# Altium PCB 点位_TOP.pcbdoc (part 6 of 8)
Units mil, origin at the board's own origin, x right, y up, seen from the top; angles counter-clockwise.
Board outline 5129 x 4161 mil, 8 copper layers (Top Layer, GND1, 内层2, VCC, 内层4, Inner5, GND2, Bottom Layer); 288 components, 452 nets, 2040 pads, 1119 vias.
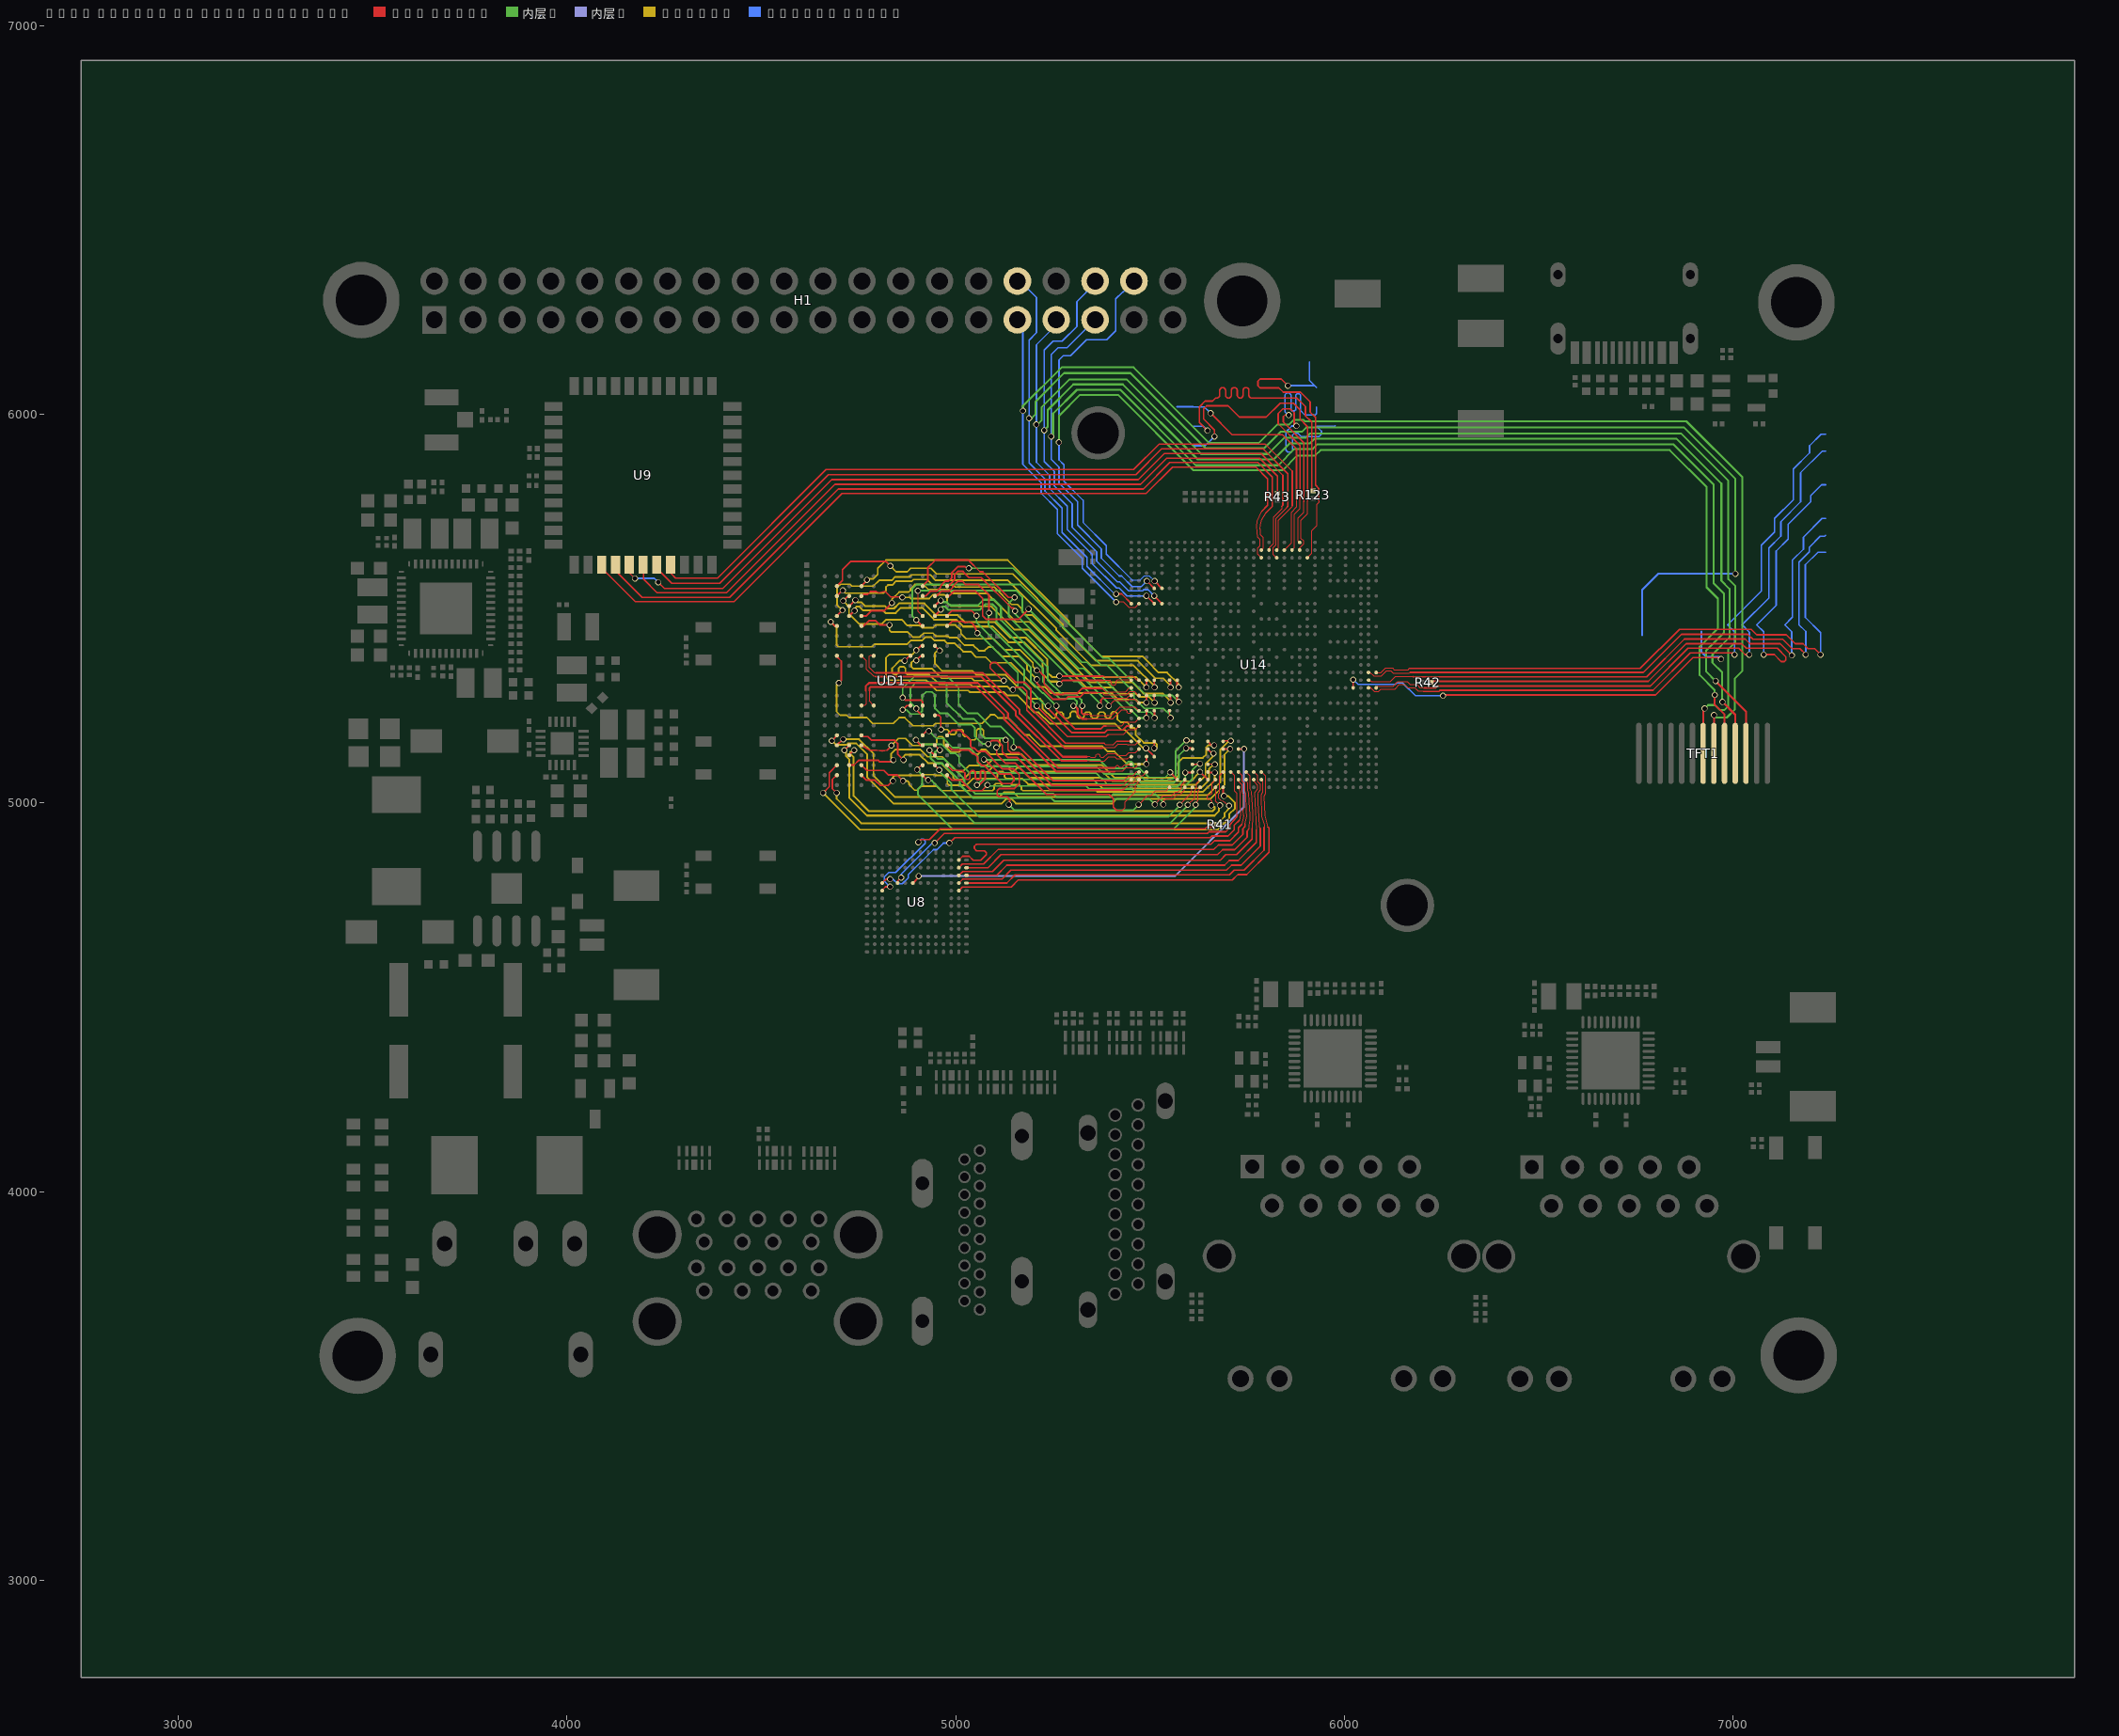
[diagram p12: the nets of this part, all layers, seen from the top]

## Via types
v1: diameter 15.75, hole 11.8, Top Layer to Bottom Layer, 496 vias
v2: diameter 15.7, hole 11.8, Top Layer to Bottom Layer, 335 vias
v3: diameter 15.75, hole 11.81, Top Layer to Bottom Layer, 279 vias
v4: diameter 24, hole 12, Top Layer to Bottom Layer, 9 vias

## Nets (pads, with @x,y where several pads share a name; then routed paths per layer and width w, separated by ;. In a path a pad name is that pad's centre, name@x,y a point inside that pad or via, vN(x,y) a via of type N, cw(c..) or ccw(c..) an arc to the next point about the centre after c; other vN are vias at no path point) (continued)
SAB5: U14.AL29 UD1.P11 | length 1061.5
  Top Layer w4: UD1.P11@4694.67,5379.22 4694.67,5376.22 4705.92,5364.97 4705.92,5314.97 v3(4699.92,5308.97)
  Top Layer w4.5: v3(5491.06,5100.23) U14.AL29@5491.06,5119.12
  Inner5 w4.5: v3(4699.92,5308.97) 4693.92,5302.97 4693.92,5234.97 4702.92,5225.97 4719.92,5225.97 4725.92,5219.97 4771.92,5219.97 4786.92,5204.97 4839.92,5204.97 4854.92,5219.97 4868.92,5219.97 4890.17,5198.72 4942.67,5198.72 4948.92,5204.97 5067.92,5204.97 5089.92,5226.97 5100.88,5226.97 5108.82,5219.03 5134.89,5218.96 5178.88,5174.97 5189.94,5174.97 5218.94,5145.97 5377.93,5145.97 5391.43,5132.47 5408.9,5132.47 5441.14,5100.23 v3(5491.06,5100.23)
SCKE0-A: U14.AM31 UD1.J4 | length 867.9
  Top Layer w3: 5432.47,5057.53 5444.82,5069.88 5455.73,5069.88 5465.6,5079.75 U14.AM31@5471.37,5079.75
  Top Layer w4.5: v3(4863.92,5270.97) 4869.92,5264.97 4910.63,5264.97 4915.14,5260.46 UD1.J4@4915.14,5251.26 ; v3(5149.31,5143.36) 5165.53,5143.36 5251.36,5057.53 5432.47,5057.53
  内层2 w4.5: v3(4863.92,5270.97) 4863.92,5295.97 4893.92,5325.97 4978.92,5325.97 5007.92,5296.97 5007.92,5252.97 5029.92,5230.97 5055.76,5230.97 5090.01,5196.72 5116.64,5196.72 5149.31,5164.05 v3(5149.31,5143.36)
SCKE0-B: U14.AN27 UD1.P4 | length 843.6
  Top Layer w3: 5382,5153.97 5387,5148.97 5404.93,5148.97 5414.45,5158.49
  Top Layer w3.8: 5414.45,5158.49 U14.AN27@5451.69,5158.49
  Top Layer w4.5: v3(4898.92,5366.97) 4911.17,5379.22 UD1.P4@4915.14,5379.22 ; v3(5123.91,5314.96) 5120.93,5314.96 5088.92,5346.97 5088.92,5355.47 5095.42,5361.97 5102.92,5361.97 5153.92,5310.97 5176.92,5310.97 5193.92,5293.97 5193.92,5242.97 5282.92,5153.97 5382,5153.97
  Inner5 w4.5: v3(4898.92,5366.97) 4892.42,5366.97 4885.92,5360.47 4885.92,5350.97 4890.92,5345.97 4938.92,5345.97 4963.92,5320.97 5041.9,5320.97 5047.91,5314.96 v3(5123.91,5314.96)
SCKE1-A: U14.AL31 UD1.J5 | length 883.1
  Top Layer w3: 5431.85,5034.48 5447.6,5050.24 5457.19,5050.24 5461.5,5054.55 5461.51,5064.09 5467.29,5069.88 5481.19,5069.88 U14.AL31@5491.06,5079.75
  Top Layer w4: v3(4863.92,5239.97) 4874.92,5250.97 4882.84,5250.97 4883.13,5251.26 UD1.J5@4883.64,5251.26
  Top Layer w4.5: v3(5083.92,5151.97) 5092.49,5160.54 5108.35,5160.54 5120.42,5148.47 5120.42,5130.96 5134.41,5116.97 5158.92,5116.97 5241.92,5033.97 5428.66,5033.97 5429.17,5034.48 5431.84,5034.48
  内层2 w4.5: v3(4863.92,5239.97) 4873.92,5239.97 4884.92,5228.97 4906.92,5228.97 4913.92,5235.97 4913.92,5275.97 4923.92,5285.97 4938.92,5285.97 4946.92,5277.97 4946.92,5242.97 4958.92,5230.97 4978.92,5230.97 5007.92,5201.97 5040.92,5201.97 5049.92,5192.97 5049.91,5170.98 5068.41,5152.47 5083.92,5152.47 v3(5083.92,5151.97)
SCKE1-B: U14.AM27 UD1.P5 | length 859.6
  Top Layer w3: 5377.52,5141.97 5407.92,5141.97 5417.54,5151.59 5440.3,5151.59 5443.27,5148.62 5461.5,5148.62 U14.AM27@5471.37,5158.49
  Top Layer w4.5: v3(4868.92,5365.97) 4882.17,5379.22 UD1.P5@4883.64,5379.22 ; v3(5147.41,5291.46) 5153.92,5297.97 5171.93,5297.97 5183.33,5286.57 5183.33,5238.57 5280.93,5140.97 5376.52,5140.97 5377.52,5141.97
  Inner5 w4.5: v3(4868.92,5365.97) 4855.92,5365.97 4836.92,5346.97 4836.92,5334.97 4840.92,5330.97 4848.74,5330.97 4853.24,5335.47 4853.24,5346.47 4857.74,5350.97 4866.74,5350.97 4871.24,5346.47 4871.24,5335.47 4875.74,5330.97 4931.92,5330.97 4956.92,5305.97 5036.39,5305.97 5042.39,5299.97 5132.92,5299.97 5141.43,5291.46 v3(5147.41,5291.46)
SCKN-A: U14.AN30 UD1.J9 | length 850.5
  Top Layer w3: UD1.J9@4757.66,5251.26 4766.13,5251.26 4769.41,5254.54 4769.41,5286.97 4768.41,5287.97 4768.41,5288.72 ; 5408.94,5090.97 5413.8,5095.83 5418.06,5095.83 5422.79,5091.1 5427.04,5091.1 5433.52,5097.58 5449.84,5097.58 U14.AN30@5451.69,5099.43
  Top Layer w5: 4768.41,5288.72 4768.41,5299.95 4777.26,5308.8 5057.09,5308.8 5134.92,5230.97 5134.92,5219.13 5263.08,5090.97 5408.94,5090.97
SCKN-B: U14.AN29 UD1.P9 | length 833.6
  Top Layer w3: UD1.P9@4757.66,5379.22 4770,5366.88 4770,5345.57 4788.36,5327.21 4791.05,5327.21 4792.05,5326.21 4794.4,5326.21 4795.4,5325.21 4795.78,5325.21 ; 5337.77,5108.97 5344.6,5108.97 5345.6,5107.97 5382.92,5107.97 5394.07,5119.12 5408.88,5119.12 5414,5114 5442.55,5113.99 5447.68,5119.12 U14.AN29@5451.69,5119.12
  Top Layer w5: 4795.78,5325.21 5065.53,5325.21 5154.92,5235.82 5154.92,5225.82 5271.77,5108.97 5337.77,5108.97
SCKP-A: U14.AM30 UD1.J8 | length 848.8
  Top Layer w3: 4778.41,5288.72 4778.41,5287.97 4777.41,5286.97 4777.41,5263.01 UD1.J8@4789.16,5251.26 ; 5408.94,5080.97 5428.91,5080.97 5437.52,5089.58 5461.51,5089.58 U14.AM30@5471.37,5099.43
  Top Layer w5: 4778.41,5288.72 4778.41,5295.8 4781.41,5298.8 5052.94,5298.8 5124.92,5226.82 5124.92,5214.98 5258.93,5080.97 5408.94,5080.97
SCKP-B: U14.AM28 UD1.P8 | length 861.4
  Top Layer w3: UD1.P8@4789.16,5379.22 4780,5379.22 4777,5376.22 4777,5349.89 4791.68,5335.21 4795.78,5335.21 ; 5337.77,5118.97 5345.92,5118.97 5348.92,5115.97 5357.36,5115.97 5360.36,5118.97 5360.36,5121.97 5363.36,5124.97 5369.36,5124.97 5372.36,5121.97 5372.36,5118.97 5375.36,5115.97 5379.6,5115.97 5390.21,5126.58 5410.63,5126.58 5410.74,5126.47 5411.42,5126.47 5416.29,5121.6 5437.54,5121.6 5444.7,5128.75 5461.32,5128.75 U14.AM28@5471.37,5138.8
  Top Layer w5: 4795.78,5335.21 5069.68,5335.21 5164.92,5239.97 5164.92,5229.97 5275.92,5118.97 5337.77,5118.97
SCS0-A: U14.AN32 UD1.H4 | length 826.4
  Top Layer w3: 5426.05,5045.97 5431.93,5045.97 5446.02,5060.06 U14.AN32@5451.69,5060.06
  Top Layer w4.5: v3(4898.92,5242.97) 4898.92,5239.97 4913.22,5225.67 UD1.H4@4915.14,5225.67 ; v3(5128.92,5161.97) 5134.92,5155.97 5134.92,5136.97 5142.92,5128.97 5163.92,5128.97 5246.92,5045.97 5426.05,5045.97
  内层2 w4.5: v3(4898.92,5242.97) 4883.92,5257.97 4883.92,5295.97 4898.92,5310.97 4972.42,5310.97 4976.92,5306.47 4976.92,5257.97 5018.42,5216.47 5046.93,5216.47 5064.42,5198.98 5064.42,5176.98 5074.43,5166.97 5123.92,5166.97 v3(5128.92,5161.97)
SCS0-B: U14.AK29 UD1.R4 | length 932.3
  Top Layer w4.5: v3(4898.92,5392.97) 4910.76,5404.81 UD1.R4@4915.14,5404.81 ; v3(5489.92,5140.97) 5510.74,5120.15 U14.AK29@5510.74,5119.12
  Inner5 w4.5: v3(4898.92,5392.97) 4887.92,5381.97 4828.92,5381.97 4820.92,5373.97 4820.92,5323.97 4828.92,5315.97 4923.92,5315.97 4950.53,5289.36 5032.49,5289.36 5036.38,5285.47 5124.42,5285.47 5132.92,5276.97 5158.92,5276.97 5202.92,5232.97 5213.99,5232.97 5242.49,5204.47 5409.42,5204.47 5425.92,5187.97 5435.92,5187.97 5482.92,5140.97 v3(5489.92,5140.97)
SCS1-A: U14.AM32 UD1.H3 | length 813.7
  Top Layer w3: 5428.92,4980.97 5434.61,4986.66 5434.61,5001.61 5461.54,5028.54 5461.54,5044.46 5471.36,5054.27 U14.AM32@5471.37,5060.06
  Top Layer w4.5: UD1.H3@4946.64,5225.67 4957.42,5225.67 4961.92,5221.17 4961.92,5189.97 v3(4962.92,5188.97) ; v3(5104.92,5142.97) 5105.92,5141.97 5105.92,5124.95 5127.9,5102.97 5152.92,5102.97 5233.92,5021.97 5394.92,5021.97 5405.92,5010.97 5405.92,4988.97 5413.92,4980.97 5428.92,4980.97
  Inner5 w4.5: v3(4962.92,5188.97) 4978.96,5188.97 4983.46,5184.47 4983.46,5180.47 4987.96,5175.97 4996.96,5175.97 5001.46,5180.47 5001.46,5184.47 5005.96,5188.97 5015.92,5188.97 5018.92,5185.97 5018.92,5175.47 5023.42,5170.97 5029.92,5170.97 5038.48,5162.41 5049.42,5162.41 5053.92,5166.91 5053.92,5186.47 5058.42,5190.97 5067.42,5190.97 5071.92,5186.47 5071.92,5171.47 5076.42,5166.97 5109.42,5166.97 5113.92,5162.47 5113.92,5147.47 5109.42,5142.97 v3(5104.92,5142.97)
SCS1-B: U14.AK27 UD1.R3 | length 886.5
  Top Layer w4: U14.AK27@5510.74,5158.49 5510.74,5141.15 v3(5510.92,5140.97)
  Top Layer w4.5: UD1.R3@4946.65,5404.81 4958.92,5392.54 v3(4958.92,5391.97)
  Inner5 w4.5: v3(4958.92,5391.97) 4952.92,5391.97 4946.92,5385.97 4946.92,5357.97 4964.92,5339.97 5043.41,5339.97 5053.41,5329.97 5129.07,5329.97 5191.06,5267.98 5217.47,5267.98 5223.67,5261.78 5223.67,5244.06 5249.76,5217.97 5254.26,5217.97 5258.76,5222.47 5258.76,5229.47 5263.26,5233.97 5272.26,5233.97 5276.76,5229.47 5276.76,5222.47 5281.26,5217.97 5290.26,5217.97 5294.76,5222.47 5294.76,5230.77 5299.27,5235.28 5308.25,5235.28 5312.76,5230.77 5312.76,5222.47 5317.26,5217.97 5326.26,5217.97 5330.76,5222.47 5330.76,5229.47 5335.26,5233.97 5344.26,5233.97 5348.76,5229.47 5348.76,5222.47 5353.26,5217.97 5362.26,5217.97 5366.76,5222.47 5366.76,5229.47 5371.26,5233.97 5380.26,5233.97 5384.76,5229.47 5384.76,5222.47 5389.26,5217.97 5395.42,5217.97 5399.92,5222.47 5399.92,5230.27 5404.74,5235.09 5411.11,5235.09 5415.92,5230.28 5415.92,5215.97 5423.92,5207.97 5440.92,5207.97 5445.92,5202.97 5445.92,5197.97 5450.17,5193.72 5458.67,5193.72 5462.92,5189.47 5462.92,5175.97 5483.92,5154.97 5513.92,5154.97 5518,5150.89 5518,5144.68 5514.3,5140.97 v3(5510.92,5140.97)
SDC0-CLK: R42.2 | length 1564.7
  Top Layer w4: R42.2@6224.51,5310 6227.51,5313 6782,5313 6879,5410 7022,5410 7034,5398 7114,5398 7136,5376 7136,5368 7132,5364 7124,5364 7106,5382 v1(7079,5382)
  Bottom Layer w4: v1(7079,5382) 7079,5440.4 7061,5458.4 7111,5508.4 7111,5648 7142,5679 7142,5717 7200,5775 7200,5791 7227.7,5818.7 7238.14,5818.7
SDC0-CMD: U14.B19 | length 1561
  Top Layer w3: U14.B19@6062.45,5315.17 6068.01,5315.17 6070.33,5312.84 6118.64,5312.84 6131.21,5325.4 6177.65,5325.4
  Top Layer w4: 6177.56,5325.26 6177.92,5324.9 6777.9,5324.9 6875,5422 7031,5422 7043,5410 7121,5410 v1(7151,5380)
  Bottom Layer w4: v1(7151,5380) 7151,5440.4 7133,5458.4 7153,5478.4 7153,5625 7181,5653 7181,5684 7229.09,5732.09 7238.14,5732.09
SDC0-D0: U14.A20 | length 1646.7
  Top Layer w3: U14.A20@6081.89,5296.31 6084.55,5298.97 6124.59,5298.97 6136.78,5311.15 6163.54,5311.15 6170.69,5304 6188,5304 6196,5296 6204,5296
  Top Layer w4: 6204,5296 6235,5296 6240,5301 6787,5301 6884,5398 7015,5398 7031,5382 v1(7042,5382)
  Bottom Layer w4: v1(7042,5382) 7042,5439.8 7023.24,5458.56 7092,5527.32 7092,5656 7123,5687 7123,5724 7174,5775 7174,5850 7229.31,5905.31 7238.14,5905.31
SDC0-D1: U14.B20 | length 1688.5
  Top Layer w3: U14.B20@6062.19,5296.31 6068.2,5296.31 6068.2,5296.1 6078.28,5286.02 6087.2,5286.02 6093.37,5292.19 6128.89,5292.19 6140.57,5303.87 6156.35,5303.87 6164.23,5296 6182,5296 6191,5287 6203,5287
  Top Layer w4: 6203,5287 6243,5287 6246,5290 6794,5290 6890,5386 7000,5386 v1(7004,5382)
  Bottom Layer w4: v1(7004,5382) 7004,5440.4 6986,5458.4 7073,5545.4 7073,5663 7107,5697 7107,5732 7155,5780 7155,5859 7197,5901 7197,5919 7226.62,5948.62 7238.14,5948.62
SDC0-D2: U14.A18 | length 1532.2
  Top Layer w3: U14.A18@6081.89,5335.71 6094.55,5335.71 6105.84,5347 6124,5347 6128,5343 6164,5343 6167,5346
  Top Layer w4: 6167,5346 6761,5346 6862,5447 7047,5447 7061,5433 7137,5433 7160,5410 7180,5410 7193,5397 7210,5397 v1(7225,5382)
  Bottom Layer w4: v1(7225,5382) 7225,5438.4 7186,5477.4 7186,5613 7218.48,5645.48 7238.14,5645.48
SDC0-D3: U14.B18 | length 1549.4
  Top Layer w3: U14.B18@6062.19,5335.71 6066.8,5335.71 6076.64,5325.84 6094.01,5325.84 6107.78,5339.61 6120.39,5339.61 6127,5333 6166,5333 6169,5336
  Top Layer w4: 6169,5336 6769,5336 6867,5434 7038,5434 7051,5421 7128,5421 7152,5397 7172,5397 v1(7187,5382)
  Bottom Layer w4: v1(7187,5382) 7187,5441.4 7170,5458.4 7170,5620 7196,5646 7196,5658 7224,5686 7235.35,5686 7238.14,5688.78
SDC0-DET: U14.D20 | length 1140.8
  Top Layer w4: U14.D20@6022.89,5296.4 v1(6022.89,5317.4) ; v1(6254,5276) 6256,5278 6801,5278 6897,5374 6965,5374 v2(6969,5370)
  Bottom Layer w4: v1(6022.89,5317.4) 6035.29,5305 6131,5305 6135,5309 6150,5309 6183,5276 v1(6254,5276)
  Bottom Layer w5: 6919,5441.49 6919,5388 6931,5376 6963,5376 v2(6969,5370)
SDC1-CLK: R43.2 U9.17 | length 1891.3
  Top Layer w4: U9.17@4197,5615.94 4197,5576 4232,5541 4411,5541 4690,5820 5476,5820 5543,5887 5782,5887 5828,5841 R43.2@5828,5797.51
SDC1-CMD: U9.16 U14.R2 | length 2095.3
  Top Layer w3: U14.R2@5806.29,5650.71 5806.29,5656.59 5816.72,5666.97 5816.72,5734.72 5839,5757 5839,5763
  Top Layer w4: U9.16@4161.57,5615.94 4161.57,5591.43 v1(4175,5578) ; v1(4235,5568) 4251,5552 4401,5552 4681,5832 5470,5832 5537,5899 5786,5899 5842,5843 5842,5766 5839,5763
  Bottom Layer w4: v1(4175,5578) 4225,5578 v1(4235,5568)
SDC1-D0: U9.18 U14.P3 | length 2057.5
  Top Layer w3: U14.P3@5825.99,5631.01 5816.12,5640.88 5816.12,5655.95 5823.22,5663.05 5823.22,5731.22 5852,5760 5852,5760.75
  Top Layer w4: U9.18@4232.43,5615.94 4232.43,5602.57 4270,5565 4393,5565 4673,5845 5464,5845 5530,5911 5791,5911 5855,5847 5855,5763.75 5852,5760.75
SDC1-D1: U9.19 U14.P2 | length 2019.1
  Top Layer w3: U14.P2@5825.99,5650.71 5829.72,5654.44 5829.72,5726.72 5866,5763 5866,5765
  Top Layer w4: U9.19@4267.87,5615.94 4267.87,5590.77 4279.64,5579 4388,5579 4667,5858 5458,5858 5523,5923 5797,5923 5866,5854 5866,5765
SDC1-D2: U9.14 U14.T3 | length 2137.9
  Top Layer w3: U14.T3@5786.59,5631.01 5776.74,5640.86 5776.74,5655.56 5783.04,5661.86 5783.04,5678.4 5777,5684.44 5776.36,5696.93 5774.27,5711.76 5775.66,5725.32 5782.5,5737.95 5788.52,5751.27
  Top Layer w4: U9.14@4090.7,5615.94 4090.7,5603.3 4176,5518 4430,5518 4708,5796 5490,5796 5558,5864 5773,5864 5803,5834 5803,5766 5788,5751
SDC1-D3: U9.15 U14.T2 | length 2097.3
  Top Layer w3: U14.T2@5786.59,5650.71 5790.2,5654.32 5790.2,5684.29 5783.77,5690.71 5783.77,5704.77 5784,5716.28 5788.64,5729.6 5797.79,5745.48
  Top Layer w4: U9.15@4126.13,5615.94 4126.13,5596.87 4194,5529 4419,5529 4698,5808 5483,5808 5551,5876 5778,5876 5815,5839 5815,5763 5798,5746
SDC2-CLK: R41.1 U8.M6 | length 1011.5
  Top Layer w4: U8.M6@4811.41,4774.52 4811.41,4776.41 4819.53,4784.53 v1(4831.42,4784.53) ; v1(4904,4899) 4911,4906 4933,4906 4961,4934 5642,4934 5646,4938 5663.8,4938 R41.1@5670.64,4944.85
  Bottom Layer w4: v1(4831.42,4784.53) 4817,4798.94 4817,4810 4828,4821 4846,4821 4921.67,4896.67 4921.67,4902.33 4917,4907 4912,4907 v1(4904,4899)
SDC2-CMD: U8.M5 U14.W33 | length 1093.4
  Top Layer w3: U14.W33@5726.25,5040.04 5728.34,5035.4 5731.12,5028.45 5731.43,5016.17 5731.43,5000.26 5732.66,4968.44 5729.65,4955.77
  Top Layer w4: U8.M5@4811.41,4794.22 4811.41,4794.41 4821.21,4804.21 v1(4831.42,4804.21) ; v1(4984,4897) 4998,4911 5655,4911 5659,4915 5701,4915 5717,4931 5717,4943 5729.75,4955.75
  Bottom Layer w4: v1(4831.42,4804.21) 4838.79,4804.21 4851,4792 4862.91,4792 4878,4807.09 4878,4815 4943,4880 4952,4880 4967.91,4895.91 4967.91,4897 v1(4984,4897)
SDC2-D0: U8.A3 U14.V32 | length 903.9
  Top Layer w3: U14.V32@5747.11,5058.35 5749.18,5053.6 5750.54,5052.31 5750.54,5033.24 5753.3,5025.74 5753.91,5004.13 5756.46,4969.3 5756.61,4957.09 5754.11,4942.85 5754.05,4933.47
  Top Layer w4: U8.A3@5027.95,4833.59 5083.59,4833.59 5117,4867 5674,4867 5687,4880 5718,4880 5750,4912 5750,4928.05 5754.29,4933.11
SDC2-D1: U8.A4 U14.U32 | length 948.8
  Top Layer w3: U14.U32@5766.98,5060.2 5766.98,5056.02 5776.61,5046.39 5776.36,5035.09 5769.09,5026.14 5769.44,5001.92 5773.38,4931.94
  Top Layer w4: U8.A4@5027.95,4813.9 5105.9,4813.9 5132,4840 5692,4840 5704,4852 5727,4852 5773.61,4898.61 5773.61,4931.76
SDC2-D2: U8.A5 U14.T32 | length 986.2
  Top Layer w3: U14.T32@5786.75,5060.37 5789.86,5057.26 5789.86,5051.25 5789.87,5050.77 5789.65,5027.27 5785.71,5020.67 5786.91,4965.86 5794,4943.09 5794,4938
  Top Layer w4: U8.A5@5027.95,4794.22 5028.17,4794 5132,4794 5153,4815 5705,4815 5717,4827 5742,4827 5793.57,4878.57 5793.57,4937.57 5794,4938
SDC2-D3: U8.B2 U14.W32 | length 968.8
  Top Layer w3: U14.W32@5727.65,5060.37 5727.65,5056.31 5737.54,5046.42 5737.54,5029.42 ; 5736.44,4945.01 5740.88,4968.17 5739.96,4981.96 5739.15,5021.81 5737.55,5029.33
  Top Layer w4: U8.B2@5008.27,4853.27 5018,4863 5035,4863 5045,4853 5065,4853 5079,4867 5079,4872 5074,4877 5054,4877 5048.33,4882.67 5048.33,4888.33 5054,4894 5656.85,4894 5665.85,4903 5706,4903 5728,4925 5728,4936.6 5736.4,4945
SDC2-D4: U8.B3 U14.W31 | length 937.5
  Top Layer w3: U14.W31@5727.65,5080.07 5737.5,5070.22 5737.5,5056.17 5744.04,5049.62 5744.04,5032.08 5746.83,5024.5 5748.05,4978.74 5749.21,4965.64 5744.93,4947.11
  Top Layer w4: U8.B3@5008.27,4833.59 5017.68,4843 5072,4843 5110,4881 5665,4881 5676,4892 5712,4892 5739,4919 5739,4933.77 5744.93,4939.7 5744.93,4947.11
SDC2-D5: U8.B4 U14.V31 | length 971.3
  Top Layer w3: U14.V31@5747.35,5080.07 5757.21,5070.21 5757.21,5036.45 5759.72,5029.45 5759.72,5029.32 5763.69,4975.14 5763.81,4965.32 5762.96,4934.72
  Top Layer w4: U8.B4@5008.27,4813.9 5018.37,4824 5095,4824 5124,4853 5681,4853 5695,4867 5723,4867 5763,4907 5763,4935
SDC2-D6: U8.B5 U14.U31 | length 1015.5
  Top Layer w3: U14.U31@5767.05,5080.07 5776.95,5070.17 5776.94,5055.25 5783.17,5049.02 5782.81,5032.72 5778.6,5027.54 5776.7,5024.33 5776.83,5002.14 5779.14,4963.67 5781.38,4938.57 5783.93,4935.4
  Top Layer w4: U8.B5@5008.27,4794.22 5018.05,4804 5119,4804 5142,4827 5697,4827 5710,4840 5735,4840 5784.03,4889.03 5784.03,4935.03
SDC2-D7: U8.B6 U14.T31 | length 1052.8
  Top Layer w3: U14.T31@5786.75,5080.07 5796.37,5070.45 5796.62,5023.49 5793.49,5017.59 5794.79,4968.06 5802.77,4938.87
  Top Layer w4: U8.B6@5008.27,4774.52 5017.74,4784 5143,4784 5161,4802 5712,4802 5726,4816 5749,4816 5806,4873 5806,4936 5803,4939
SDC2-DS: U8.H5 U14.W28 | length 1098
  Top Layer w5: U8.H5@4890.15,4794.22 4905,4809.06 v1(4905,4812) ; U14.W28@5727.61,5138.93 v1(5742,5138.93)
  内层4 w5: v1(4905,4812) 5564,4812 5742,4990 v1(5742,5138.93)
SDC2-RST: U8.K5 U14.Y31 | length 1079.3
  Top Layer w3: U14.Y31@5707.95,5080.07 5717.77,5070.25 5717.77,5030.88 5724.55,5024.1 5724.55,4968.45
  Top Layer w4: U8.K5@4850.78,4794.22 4850.78,4798.78 v1(4860,4808) ; v1(4946,4897) 4971,4922 5648,4922 5652,4926 5695,4926 5706,4937 5706,4945 5723.09,4963.56 5724.47,4968.59
  Bottom Layer w4: v1(4860,4808) 4860,4817 4940,4897 v1(4946,4897)
SDQ0: U14.AE28 UD1.E4 | length 860.7
  Top Layer w4.5: v3(4897.92,5161.97) 4897.92,5160.97 4909.99,5148.9 UD1.E4@4915.14,5148.9 ; v3(5592.97,5141.23) 5606.74,5141.23 U14.AE28@5609.17,5138.8
  内层2 w4.5: v3(4897.92,5161.97) 4899.92,5161.97 4910.92,5150.97 4963.92,5150.97 4986.89,5128 4999.89,5128 5008.92,5118.97 5008.92,5103.97 5035.42,5077.47 5360.76,5077.47 5376.76,5061.47 5467.42,5061.47 5477.36,5051.53 5560.48,5051.53 5574.92,5065.97 5574.92,5123.18 v3(5592.97,5141.23)
SDQ1: U14.AE27 UD1.F4 | length 841.5
  Top Layer w3: v3(5593.96,5161.23) 5596.71,5158.49 U14.AE27@5609.17,5158.49
  Top Layer w4.5: UD1.F4@4915.14,5174.49 4924.62,5183.97 4929.92,5183.97 4930.87,5184.92 v3(4931.4,5184.92)
  内层2 w3: 5483.92,5061.97 5486.92,5058.97 5544.92,5058.97 5547.92,5061.97
  内层2 w4.5: v3(4931.4,5184.92) 4950.35,5165.97 4968.92,5165.97 4992.42,5142.47 5008.76,5142.47 5010.78,5140.45 5036.55,5140.45 5057.17,5119.83 5057.17,5102.72 5065.92,5093.97 5362.92,5093.97 5382.42,5074.47 5471.42,5074.47 5483.92,5061.97 ; 5547.92,5061.97 5557.92,5061.97 5565.92,5069.97 5565.92,5133.97 5593.18,5161.23 v3(5593.96,5161.23)
SDQ2: U14.AG32 UD1.E2 | length 880.5
  Top Layer w4.5: UD1.E2@4978.13,5148.9 4990.47,5136.56 5033.33,5136.56 5042.89,5127 5048,5127 5056.92,5118.08 5056.92,5106.97 5066.92,5096.97 5072.92,5096.97 5119.92,5049.97 5142.92,5049.97 5149.92,5056.97 5149.92,5065.97 5140.92,5074.97 5112.92,5074.97 5075.92,5111.97 v3(5072.92,5111.97) ; v3(5552,5079) 5569.8,5061.17 U14.AG32@5569.8,5060.06
  内层2 w3: 5494.92,5067.97 5496.92,5065.97 5538.97,5065.97 v3(5552,5079)
  内层2 w4.5: v3(5072.92,5111.97) 5073.92,5110.97 5370.92,5110.97 5392.92,5088.97 5434.72,5088.97 5439.22,5093.47 5439.22,5101.47 5443.72,5105.97 5452.72,5105.97 5457.22,5101.47 5457.22,5093.47 5461.72,5088.97 5473.92,5088.97 5494.92,5067.97
SDQ3: U14.AH33 UD1.F2 | length 840.6
  Top Layer w3: v3(5470.92,4995.97) 5492.94,5018 5501,5018 5514.01,5031.01 5540.73,5031.01 U14.AH33@5550.11,5040.38
  Top Layer w4.5: UD1.F2@4978.13,5174.49 4990.63,5187 5012.89,5187 5038.92,5160.97 5038.92,5145.97 5043.42,5141.47 5047.92,5141.47 5056.42,5132.97 5075.26,5132.97 5120.26,5087.97 5148.92,5087.97 5163.92,5072.97 5163.92,5049.97 5150.92,5036.97 5111.92,5036.97 5106.92,5031.97 5106.92,5020.97 5111.92,5015.97 5132.92,5015.97 5138.92,5009.97 5138.92,4997.97 v3(5136.92,4995.97)
  内层2 w4.5: v3(5136.92,4995.97) 5151.67,4981.22 5456.17,4981.22 v3(5470.92,4995.97)
SDQ4: U14.AE30 UD1.B2 | length 740.8
  Top Layer w4.5: UD1.B2@4978.13,5072.13 4991.29,5058.97 5013.92,5058.97 5040.92,5031.97 5067.67,5031.97 v3(5081.92,5046.22) ; U14.AE30@5609.17,5099.43 5627.38,5099.43 v3(5628.92,5100.97)
  内层2 w4.5: v3(5081.92,5046.22) 5084.17,5043.97 5335.92,5043.97 5343.92,5035.97 5453.92,5035.97 5456.92,5032.97 5579.92,5032.97 5608.92,5061.97 5608.92,5084.97 5624.92,5100.97 v3(5628.92,5100.97)
SDQ5: U14.AD32 UD1.B4 | length 831.9
  Top Layer w3: v3(5597.44,4995.51) 5613.77,5011.84 5613.77,5031.09 5618.99,5036.31 5618.99,5050.2 U14.AD32@5628.85,5060.06
  Top Layer w4.5: UD1.B4@4915.14,5072.13 4927.3,5059.97 4928.92,5059.97 v3@4929.54,5059.35
  内层2 w4.5: v3(4929.63,5059.35) 4931.31,5057.67 4939.22,5057.67 5048.67,4948.22 5552.15,4948.22 5597.44,4993.51 v3(5597.44,4995.51)
SDQ6: U14.AE31 UD1.C2 | length 817.4
  Top Layer w4.5: UD1.C2@4978.13,5097.72 4991.88,5083.97 5017.17,5083.97 5023.92,5077.22 5023.92,5064.97 5027.92,5060.97 5033.92,5060.97 5036.92,5063.97 5036.92,5079.47 5041.42,5083.97 5046.42,5083.97 5050.92,5079.47 5050.92,5063.97 5054.27,5060.62 5060.92,5060.62 5063.92,5063.62 5063.92,5080.97 5066.92,5083.97 5071.92,5083.97 5075.92,5079.97 5075.92,5060.97 5061.17,5046.22 v3(5054.92,5046.22) ; v3(5590.85,5078.25) 5607.68,5078.25 U14.AE31@5609.17,5079.75
  内层2 w4.5: v3(5054.92,5046.22) 5069.67,5060.97 5353.92,5060.97 5366.92,5047.97 5464.92,5047.97 5470.92,5041.97 5568.92,5041.97 5590.85,5063.9 v3(5590.85,5078.25)
SDQ7: U14.AD33 UD1.C4 | length 924.5
  Top Layer w3: v3(5617.54,4995.41) 5617.54,5000.4 5621.99,5004.85 5621.99,5029.2 5625.85,5033.06 5625.85,5037.38 U14.AD33@5628.85,5040.38
  Top Layer w4.5: v3(4900.92,5085.97) 4912.67,5097.72 UD1.C4@4915.14,5097.72
  内层2 w4.5: v3(4900.92,5085.97) 4913.92,5072.97 4913.92,5045.97 4902.92,5034.97 4902.92,5021.97 4993.17,4931.72 5559.67,4931.72 5617.54,4989.59 v3(5617.54,4995.41)
SDQ8: U14.AC27 UD1.E9 | length 1106.2
  Top Layer w4.5: UD1.E9@4757.8,5148.53 4779,5136 4797,5136 4811,5134 4824,5136 v3(4834.92,5147.97) ; U14.AC27@5648.54,5158.49 5658.8,5148.23 v3(5664.97,5148.23)
  Inner5 w4.5: v3(4834.92,5147.97) 4852.92,5165.97 4870.92,5165.97 4888.92,5147.97 4913.92,5147.97 4916.92,5150.97 4947.42,5150.97 4951.92,5155.47 4951.92,5166.47 4956.42,5170.97 4965.42,5170.97 4969.92,5166.47 4969.92,5149.97 4988.92,5130.97 5008.92,5130.97 5015.92,5137.97 5040.15,5137.97 5044.65,5133.47 5044.65,5130.47 5049.15,5125.97 5058.15,5125.97 5062.65,5130.47 5062.65,5133.47 5067.15,5137.97 5076.92,5137.97 5088.92,5125.97 5169.02,5125.97 5197.02,5097.97 5375.93,5097.97 5409.18,5064.72 5567.67,5064.72 5572.92,5069.97 5572.92,5103.97 5584.92,5115.97 5635.92,5115.97 5644.92,5124.97 5644.92,5143.72 5649.43,5148.23 v3(5664.97,5148.23)
SDQ9: U14.AC28 UD1.F9 | length 1107.7
  Top Layer w4.5: UD1.F9@4757.66,5174.49 4761.18,5170.97 4774.3,5170.97 4783.3,5161.97 4841.92,5161.97 4850.92,5152.97 4850.92,5125.97 v3(4865.92,5110.97) ; U14.AC28@5648.54,5138.8 5659.73,5127.61 v3(5663.64,5127.61)
  Inner5 w4.5: v3(4865.92,5110.97) 4865.92,5119.47 4870.42,5123.97 4907.92,5123.97 4928.92,5102.97 4961.92,5102.97 4993.92,5070.97 4993.92,5065.47 4998.42,5060.97 5020.08,5060.97 5039,5079.89 5082.84,5079.89 5098.92,5095.97 5134.42,5095.97 5138.92,5091.47 5138.92,5085.97 5143.92,5080.97 5148.92,5080.97 5158.23,5090.28 5164.61,5090.28 5189.92,5064.97 5373.92,5064.97 5391.92,5046.97 5618.92,5046.97 5642.92,5070.97 5642.92,5100.97 5663.64,5121.69 v3(5663.64,5127.61)
SDQ10: U14.AC30 UD1.B9 | length 1059.2
  Top Layer w3: U14.AC30@5648.54,5099.43 5648.72,5099.25 v3(5666.84,5099.25)
  Top Layer w4.5: UD1.B9@4757.66,5072.13 4770.82,5058.97 4792.92,5058.97 4806.92,5044.97 4826.92,5044.97 v3(4838.92,5056.97)
  Inner5 w4.5: v3(4838.92,5056.97) 4838.92,5066.47 4843.42,5070.97 4908.92,5070.97 4910.92,5072.97 4945.92,5072.97 4947.92,5070.97 4971.92,5070.97 4978.92,5063.97 4978.92,5050.47 4983.42,5045.97 5028.42,5045.97 5045.84,5063.39 5103.02,5063.39 5107.52,5067.89 5107.52,5076.47 5112.02,5080.97 5121.02,5080.97 5125.52,5076.47 5125.52,5067.89 5130.02,5063.39 5171.5,5063.39 5186.42,5048.47 5367.41,5048.47 5377.91,5037.97 5630.92,5037.97 5651.92,5058.97 5651.92,5086.97 5664.2,5099.25 v3(5666.84,5099.25)
SDQ11: U14.AC31 UD1.C9 | length 1026.9
  Top Layer w4.5: UD1.C9@4757.66,5097.72 4771.41,5083.97 4815.92,5083.97 4827.92,5071.97 4849.92,5071.97 v3(4864.92,5056.97) ; U14.AC31@5648.54,5079.75 5650.03,5078.25 v3(5666.85,5078.25)
  Inner5 w4.5: v3(4864.92,5056.97) 4875.92,5056.97 4880.42,5052.47 4880.42,5047.47 4894.73,5033.16 4901.11,5033.16 4910.92,5042.97 4951.92,5042.97 4962.92,5031.97 5094.92,5031.97 5098.92,5035.97 5098.92,5045.39 5103.42,5049.89 5116,5049.89 5122.92,5042.97 5139.92,5042.97 5143.92,5046.97 5164.42,5046.97 5168.92,5042.47 5168.92,5035.97 5172.92,5031.97 5361.29,5031.97 5364.29,5028.97 5636.92,5028.97 5666.85,5058.9 v3(5666.85,5078.25)
SDQ12: U14.AA33 UD1.C11 | length 1287.4
  Top Layer w4.5: v3(4658.92,5025.97) 4675,5042.06 4675,5078.06 UD1.C11@4694.67,5097.72 ; U14.AA33@5687.91,5040.38 5687.91,5020.64 v3(5690.58,5017.97)
  Inner5 w4.5: v3(4658.92,5025.97) 4753.42,4931.47 5674.42,4931.47 5703.92,4960.97 5703.92,4970.97 5718.92,4985.97 5718.92,4999.97 5700.92,5017.97 v3(5690.58,5017.97)
SDQ13: U14.AA31 UD1.B11 | length 1240.4
  Top Layer w3: 5681.64,5007.39 ccw(c5681.37,5007.39) 5681.56,5007.57 ; U14.AA31@5687.91,5079.75 5678.08,5069.92 5678.08,5025.08 5676,5023 5676,5013.13 5681.56,5007.57 ; v3(5703.39,4992.97) 5687.28,5005.12 5681.56,5007.57
  Top Layer w4.5: v3(4693.92,5025.97) 4683,5036.89 4683,5060.47 UD1.B11@4694.67,5072.13
  Inner5 w4.5: v3(4693.92,5025.97) 4693.92,5010.97 4756.92,4947.97 5674.92,4947.97 5691.92,4964.97 5691.92,4973.98 5703.39,4985.45 v3(5703.39,4992.97)
SDQ14: U14.AA28 UD1.F11 | length 1280.2
  Top Layer w4: U14.AA28@5687.91,5138.8 5705.77,5138.8 v3(5706.22,5139.25)
  Top Layer w4.5: v3(4681.78,5160.09) 4694.67,5172.98 UD1.F11@4694.67,5174.49
  Inner5 w4.5: v3@4681.92,5160.06 4692.01,5149.97 4719.92,5149.97 4723.11,5153.16 4744.73,5153.16 4772.92,5124.97 4772.92,5065.97 4839.92,4998.97 5118.92,4998.97 5130.92,5010.97 5142.92,5010.97 5154.92,4998.97 5402.92,4998.97 5414.92,5010.97 5655.92,5010.97 5691.92,5046.97 5691.92,5124.95 v3(5706.22,5139.25)
SDQ15: U14.AA27 UD1.E11 | length 1253.7
  Top Layer w4.5: UD1.E11@4694.67,5148.9 4709.74,5163.97 v3(4710.92,5163.97) ; U14.AA27@5687.91,5158.49 5689.39,5159.97 v3(5707.92,5159.97)
  Inner5 w4.5: v3(4710.92,5163.97) 4751.92,5163.97 4788.92,5126.97 4788.92,5070.97 4844.79,5015.1 5111.7,5015.1 5124.08,5027.47 5149.76,5027.47 5161.76,5015.47 5398.42,5015.47 5402.92,5019.97 5647.92,5019.97 5680.92,5052.97 5680.92,5136.97 5703.92,5159.97 v3(5707.92,5159.97)
SDQ16: U14.AM25 UD1.U2 | length 658.2
  Top Layer w3: 5391.61,5175.47 5431.21,5175.47 5443.78,5188.04 5461.54,5188.04 U14.AM25@5471.37,5197.86
  Top Layer w4.5: UD1.U2@4978.27,5455.62 4990,5466 4991,5467 5014,5468 5025,5464 5035,5466 5044,5462 5046,5458 5051,5451 v3(5055.92,5436.97) ; v3(5208.92,5249.97) 5287.92,5170.97 5387.11,5170.97 5391.61,5175.47
  内层2 w4.5: v3(5055.92,5436.97) 5058.92,5436.97 5160.42,5335.47 5160.42,5299.13 5208.92,5250.63 v3(5208.92,5249.97)
SDQ17: U14.AN25 UD1.V2 | length 651.2
  Top Layer w4.5: UD1.V2@4978.13,5481.58 4991.38,5494.83 5041.06,5494.83 v3(5053.92,5481.97) ; v3(5237.92,5249.97) 5238.92,5248.97 5238.92,5241.97 5299.92,5180.97 5382.92,5180.97 5389.92,5187.97 5429.92,5187.97 5439.81,5197.86 U14.AN25@5451.69,5197.86
  内层2 w4.5: v3(5053.92,5481.97) 5053.92,5465.31 5176.92,5342.31 5176.92,5305.97 5232.92,5249.97 v3(5237.92,5249.97)
SDQ18: U14.AH23 UD1.U4 | length 949.5
  Top Layer w3: U14.AH23@5550.1,5237.22 5550.1,5221.83 v3(5552.96,5218.97)
  Top Layer w4.5: v3(4899,5471) 4914.01,5455.99 UD1.U4@4915.14,5455.99
  内层2 w4.5: v3(4899,5471) 4888.92,5481.08 4888.92,5551.97 4898.92,5561.97 5166.93,5561.97 5373.93,5354.97 5388.92,5354.97 5458.92,5284.97 5458.92,5269.97 5485.42,5243.47 5534.53,5243.47 5552.96,5225.04 v3(5552.96,5218.97)
SDQ19: U14.AK23 UD1.Y2 | length 743.2
  Top Layer w4.5: UD1.Y2@4978.13,5532.76 4983.36,5532.76 4995.6,5545 5050.89,5545 5069.42,5526.47 5069.42,5482.13 5079.08,5472.47 5161.42,5472.47 v3(5187.92,5498.97) ; U14.AK23@5510.74,5237.23 5511.96,5236.01 v3(5511.96,5218.97)
  内层2 w4.5: v3(5187.92,5498.97) 5187.92,5498.62 5324.57,5361.97 5337.92,5361.97 5448.92,5250.97 5453.92,5250.97 5470.92,5233.97 5500.92,5233.97 5511.96,5222.93 v3(5511.96,5218.97)
SDQ20: U14.AL23 UD1.V4 | length 834.6
  Top Layer w3: v3(4902.92,5545.97) 4902.92,5493.8 UD1.V4@4915.14,5481.58
  Top Layer w4: v3(5491.05,5219.06) U14.AL23@5491.05,5237.22
  内层2 w4.5: v3(4902.92,5545.97) 4903.92,5546.97 5154.91,5546.97 5171.42,5530.46 5171.42,5491.78 5316.74,5346.46 5330.09,5346.46 5435.58,5240.97 5448.92,5240.97 5470.83,5219.06 v3(5491.05,5219.06)
SDQ21: U14.AM22 UD1.AA2 | length 681
  Top Layer w3: v3(5393.92,5249.97) 5406.94,5263 5442.94,5263 5446.68,5266.73 5461.54,5266.73 U14.AM22@5471.37,5256.91
  Top Layer w4.5: UD1.AA2@4978.13,5558.35 4981.29,5558.35 4997.92,5574.98 4997.92,5587.97 5005.94,5596 5018.89,5596 5034.92,5579.97 5065.92,5579.97 5143.92,5501.97 5148.42,5501.97 5152.92,5497.47 v3(5152.92,5493.97)
  内层2 w4.5: v3(5152.92,5493.97) 5152.92,5486.94 5309.91,5329.95 5320.94,5329.95 5393.92,5256.97 v3(5393.92,5249.97)
SDQ22: U14.AN21 UD1.AA4 | length 813
  Top Layer w3: 5379.59,5270.64 5440.6,5270.64 5446.56,5276.6 U14.AN21@5451.69,5276.6
  Top Layer w4.5: UD1.AA4@4915.14,5558.35 4928.92,5572.13 4928.92,5605.97 4947.92,5624.97 5032.92,5624.97 5062.92,5594.97 5069.92,5594.97 5135.92,5528.97 v3(5151.92,5528.97) ; v3(5370.92,5249.97) 5372.92,5249.97 5373.92,5250.97 5373.92,5264.97 5379.59,5270.64
  内层2 w4.5: v3(5151.92,5528.97) 5136.42,5513.47 5136.42,5480.1 5303.08,5313.44 5314.11,5313.44 5370.92,5256.63 v3(5370.92,5249.97)
SDQ23: U14.AG21 UD1.Y4 | length 872.4
  Top Layer w4: v3(5574.33,5260.04) 5573.79,5260.04 5569.79,5264.04 5569.79,5266.82 ; 5569.79,5266.82 5569.8,5276.61 5569.79,5266.82
  Top Layer w4.5: UD1.Y4@4915.14,5532.76 4922.63,5532.76 4934.84,5544.97 4950.84,5544.97 4961.84,5555.97 4961.84,5558.89 4973.92,5570.97 4981.97,5570.97 4989.92,5578.92 4989.92,5591.97 5005.92,5607.97 5024.92,5607.97 5028.89,5604 v3(5034,5604)
  内层2 w4.5: v3(5034,5604) 5147.89,5604 5378.92,5372.97 5393.92,5372.97 5489.89,5277 5557.37,5277 v3(5574.33,5260.04)
SDQ24: U14.AG19 UD1.AA9 | length 1018.4
  Top Layer w4: U14.AG19@5569.79,5315.96 5569.79,5301.88 v3(5573.96,5297.71)
  Top Layer w4.5: UD1.AA9@4757.66,5558.35 4771.92,5572.61 v3(4771.92,5573.97)
  Inner5 w4.5: v3(4771.92,5573.97) 4774.92,5576.97 4788.92,5576.97 4799.92,5587.97 4799.92,5603.97 4820.92,5624.97 5134.26,5624.97 5291.92,5467.31 5291.92,5460.97 5375.92,5376.97 5481.92,5376.97 5493.92,5364.97 5493.92,5364.47 5522.42,5335.97 5543.92,5335.97 5573.96,5305.93 v3(5573.96,5297.71)
SDQ25: U14.AH19 UD1.AA11 | length 1069.6
  Top Layer w4.5: UD1.AA11@4694.67,5558.35 4708.92,5572.6 4708.92,5599.97 4730.92,5621.97 4819.92,5621.97 v3(4831.92,5609.97) ; U14.AH19@5550.12,5316.05 U14.AH19@5552.96,5313.21 ; v3(5552.96,5297.71) U14.AH19@5552.96,5313.12
  Inner5 w4.5: v3(4831.92,5609.97) 4846.92,5594.97 4875.92,5594.97 4884.92,5603.97 4936.92,5603.97 4951.42,5589.47 5146.42,5589.47 5275.42,5460.47 5275.42,5451.47 5360.92,5365.97 5468.92,5365.97 5513.92,5320.97 5533.92,5320.97 5552.96,5301.93 v3(5552.96,5297.71)
SDQ26: U14.AK19 UD1.V11 | length 1061.4
  Top Layer w4: U14.AK19@5510.73,5315.96 5510.73,5298.94 v3(5511.96,5297.71)
  Top Layer w4.5: UD1.V11@4694.67,5481.58 4708.92,5495.83 v3(4708.92,5495.97)
  Inner5 w4.5: v3(4708.92,5495.97) 4694.92,5509.97 4694.92,5553.97 4703.92,5562.97 4727.92,5562.97 4732.92,5557.97 4788.29,5557.97 4803.29,5572.97 4835.92,5572.97 4844.92,5581.97 4881.92,5581.97 4886.92,5586.97 4934.92,5586.97 4948.92,5572.97 5134.92,5572.97 5258.92,5448.97 5258.92,5444.63 5349.57,5353.97 5457.92,5353.97 5511.96,5299.93 v3(5511.96,5297.71)
SDQ27: U14.AL19 UD1.Y11 | length 961.4
  Top Layer w4.5: UD1.Y11@4694.67,5532.76 4708.88,5546.97 v3(4709.92,5546.97) ; v3(5491.05,5297.8) U14.AL19@5491.05,5315.96
  Inner5 w4.5: v3(4709.92,5546.97) 4716.92,5539.97 4814.92,5539.97 4820.82,5545.88 4820.82,5555.88 4825.92,5560.97 4836.92,5560.97 4846.92,5570.97 4887.92,5570.97 4891.92,5574.97 4926.92,5574.97 4940.92,5560.97 4993.92,5560.97 4999.42,5555.47 5099.42,5555.47 5143.92,5510.97 5158.92,5510.97 5170.92,5498.97 5170.92,5493.97 5180.92,5483.97 5196.24,5483.97 5356.24,5323.97 5464.88,5323.97 v3(5491.05,5297.8)
SDQ28: U14.AM21 UD1.U9 | length 856.7
  Top Layer w3: 5362.25,5283.97 5376.92,5283.97 5382.89,5278 5438.76,5278 5447.18,5286.42 5461.55,5286.42 U14.AM21@5471.37,5276.6
  Top Layer w4.5: UD1.U9@4757.66,5455.99 4763.94,5455.99 4776.92,5468.97 4794.92,5468.97 4805.92,5457.97 v3(4829.92,5457.97) ; v3(5209.02,5318.07) 5209.02,5308.87 5250.92,5266.97 5282.92,5266.97 5288.92,5272.97 5319.92,5272.97 5330.92,5283.97 5362.25,5283.97
  Inner5 w4.5: v3(4829.92,5457.97) 4829.92,5444.47 4834.42,5439.97 4876.92,5439.97 4889.92,5426.97 4907.92,5426.97 4917.92,5436.97 4941.92,5436.97 4949.92,5428.97 4980.92,5428.97 4983.92,5425.97 5002.92,5425.97 5022.92,5405.97 5045.6,5405.97 5059.6,5391.97 5074.92,5391.97 5083.92,5400.97 5095.58,5400.97 5119.08,5377.47 5162.42,5377.47 5183.92,5355.97 5183.92,5342.63 5208.48,5318.07 v3(5209.02,5318.07)
SDQ29: U14.AL21 UD1.U11 | length 983.1
  Top Layer w4.5: v3(4678.84,5465.97) 4688.82,5455.99 UD1.U11@4694.67,5455.99 ; v3(5491.05,5258.43) U14.AL21@5491.05,5276.59
  Inner5 w4.5: v3(4678.84,5465.97) 4693.92,5450.89 4693.92,5406.47 4698.42,5401.97 4784.92,5401.97 4791.92,5408.97 4875.92,5408.97 4884.92,5417.97 4913.97,5417.97 4923,5427 4936.89,5427 4945.92,5417.97 4971.92,5417.97 4978.92,5410.97 4997.92,5410.97 5019.42,5389.47 5038.76,5389.47 5052.76,5375.47 5077.42,5375.47 5091.92,5360.97 5141.92,5360.97 5203.91,5298.98 5228.91,5298.98 5245.42,5282.47 5402.42,5282.47 5418.42,5266.47 5464.42,5266.47 5472.46,5258.43 v3(5491.05,5258.43)
SDQ30: U14.AK21 UD1.Y9 | length 912.8
  Top Layer w4: UD1.Y9@4757.66,5532.76 4761.89,5537 4774,5537 4781,5544 4796,5544 4803,5541 4818.89,5544 4832.92,5529.97 4861.92,5529.97 v3(4862.92,5528.97) ; U14.AK21@5510.73,5276.59 5510.73,5259.57 v3(5511.96,5258.34)
  Inner5 w4.5: v3(4862.92,5528.97) 4881.92,5528.97 4884.92,5525.97 4931.92,5525.97 4941.92,5535.97 4970.92,5535.97 4977.92,5528.97 4977.92,5515.97 4987.92,5505.97 5091.53,5505.97 5151.53,5445.97 5187.56,5445.97 5336.56,5296.97 5404.92,5296.97 5420.92,5280.97 5463.92,5280.97 5471.89,5273 5497.3,5273 v3(5511.96,5258.34)
SDQ31: U14.AH21 UD1.V9 | length 979.8
  Top Layer w4.5: UD1.V9@4757.66,5481.58 4770.54,5481.58 4783.72,5494.76 4816.71,5494.76 4835.92,5513.97 v3(4835.92,5514.97) ; v3(5552.96,5258.34) U14.AH21@5552.96,5273.75
  Inner5 w4.5: v3(4835.92,5514.97) 4835.92,5523.97 4854.92,5542.97 4879.42,5542.97 4883.92,5547.47 4883.92,5550.97 4894.92,5561.97 4916.91,5561.97 4929.91,5548.97 4982.92,5548.97 4992.92,5538.97 5081.87,5538.97 5154.87,5465.97 5190.9,5465.97 5345.9,5310.97 5453.92,5310.97 5482.89,5282 5532.89,5282 5552.96,5261.93 v3(5552.96,5258.34)
SDQM0: U14.AE33 UD1.C3 | length 767.8
  Top Layer w3: v3(5576.61,4995.51) 5605.84,5024.74 5607.28,5033.54 U14.AE33@5608.9,5040.65
  Top Layer w4.5: UD1.C3@4946.64,5097.72 4957.92,5086.44 v3(4957.92,5084.97)
  内层2 w4.5: v3(4957.92,5084.97) 4957.92,5081.97 4988.92,5050.97 4988.92,5035.97 5060.17,4964.72 5547.65,4964.72 5576.44,4993.51 5576.44,4995.34 v3(5576.61,4995.51)
SDQM1: U14.AC32 UD1.C10 | length 1036.8
  Top Layer w4.5: UD1.C10@4726.16,5097.72 4738.67,5097.72 4750.92,5109.97 4800.92,5109.97 4804.92,5105.97 4834.92,5105.97 v3(4839.92,5110.97) ; v3(5628.92,5079.97) 5648.54,5060.35 U14.AC32@5648.54,5060.06
  Inner5 w4.5: v3(4839.92,5110.97) 4833.92,5116.97 4833.92,5125.97 4845.92,5137.97 4908.92,5137.97 4927.92,5118.97 4965.92,5118.97 5003.92,5080.97 5018.92,5080.97 5034.34,5096.39 5079.34,5096.39 5093.92,5110.97 5164.92,5110.97 5194.42,5081.47 5377.42,5081.47 5402.92,5055.97 5604.92,5055.97 v3(5628.92,5079.97)
SDQM2: U14.AM24 UD1.Y3 | length 785.1
  Top Layer w3: 5386.92,5197.97 5425.92,5197.97 5435.43,5207.49 5461.31,5207.49 U14.AM24@5471.37,5217.54
  Top Layer w4.5: UD1.Y3@4946.64,5532.76 4950.71,5532.76 4962.92,5544.97 4982.97,5544.97 4993,5555 4993,5557.45 5006.55,5571 5016.89,5571 5025.92,5561.97 5058.92,5561.97 5085.92,5534.97 v3(5085.92,5488.97) ; v3(5258.92,5249.97) 5258.92,5238.53 5306.48,5190.97 5373.92,5190.97 5380.92,5197.97 5386.92,5197.97
  内层2 w4.5: v3(5085.92,5488.97) 5084.92,5487.97 5084.92,5458.02 5086.92,5456.02 5086.92,5455.65 5193.92,5348.65 5193.92,5312.31 5223.26,5282.97 5225.92,5282.97 v3(5258.92,5249.97)
SDQM3: U14.AN20 UD1.Y10 | length 923.7
  Top Layer w3: 5376.92,5295.24 5386.16,5286 5437.15,5286 5447.44,5296.28 U14.AN20@5451.69,5296.28
  Top Layer w4.5: v3(4710.92,5519.97) 4723.71,5532.76 UD1.Y10@4726.16,5532.76 ; v3(5208.92,5340.97) 5212.92,5340.97 5227.92,5325.97 5227.92,5305.97 5254.92,5278.97 5276.92,5278.97 5279.92,5281.97 5312.92,5281.97 5326.19,5295.24 5376.92,5295.24
  Inner5 w4.5: v3(4710.92,5519.97) 4725.92,5504.97 4725.92,5486.97 4751.92,5460.97 4810.92,5460.97 4821.92,5471.97 4861.03,5471.97 4876.03,5456.97 4907.92,5456.97 4913.92,5450.97 4941.92,5450.97 4948.92,5457.97 4999.92,5457.97 5013.92,5443.97 5013.92,5435.97 5027.17,5422.72 5097.17,5422.72 5125.92,5393.97 5165.92,5393.97 5198.92,5360.97 5198.92,5350.97 v3(5208.92,5340.97)
SDQS0N: U14.AF33 UD1.E3 | length 777.5
  Top Layer w3: v3(5534.44,4996.51) 5534.44,5004.49 5539.92,5009.97 5558.17,5009.97 5569.17,5020.97 5576.24,5020.97 5587.66,5032.39 5587.66,5038.56 U14.AF33@5589.48,5040.38
  Top Layer w3.8: UD1.E3@4946.64,5148.9 v3(4959.44,5136.1)
  内层2 w5: v3(4959.44,5136.1) 4952.41,5136.08 4947.42,5131.05 4947.42,5120.5 4954.48,5113.47 4970.7,5113.47 5022.42,5061.75 5022.42,5051.74 5049.94,5024.22 5250.75,5024.22 5259,5015.97 5398.91,5015.97 5405.41,5022.47 5514.59,5022.47 5534.44,5002.62 v3(5534.44,4996.51)
SDQS0P: U14.AF32 UD1.D3 | length 789.5
  Top Layer w3: v3(5512.44,4996.51) 5532.92,5017 5555,5017 5566,5028 5571.94,5028 5579.92,5035.97 5579.92,5044.97 5589.48,5054.53 U14.AF32@5589.48,5060.06
  Top Layer w5: v3(4932.92,5135.97) 4945.58,5123.31 UD1.D3@4946.64,5123.31
  内层2 w5: v3(4932.92,5135.97) 4935.89,5133.02 4935.92,5115.72 4949.73,5101.97 4965.93,5101.97 5010.92,5056.98 5010.92,5046.97 5045.17,5012.72 5245.98,5012.72 5254.23,5004.47 5403.68,5004.47 5410.18,5010.97 5497.98,5010.97 v3(5512.44,4996.51)
SDQS1N: U14.AB33 UD1.E10 | length 1187.6
  Top Layer w3: U14.AB33@5668.22,5040.38 5668.22,5005.67 v3(5679.92,4993.97)
  Top Layer w5: v3(4713.92,5135.97) 4726.16,5148.21 UD1.E10@4726.16,5148.9
  Inner5 w5: v3(4713.92,5135.97) 4713.92,5135.85 4717.9,5131.87 4717.9,5120.99 4726.42,5112.47 4726.42,5013.47 4772.17,4967.72 5666.18,4967.72 5677.92,4979.46 5677.92,4991.97 v3(5679.92,4993.97)
SDQS1P: U14.AB32 UD1.D10 | length 1194.4
  Top Layer w3: v3(5657.92,4993.97) 5657.92,4998.97 5658.42,4999.47 5658.42,5005.66 5655.42,5008.66 5650.06,5008.66 5646.18,5012.54 5646.18,5016.79 5650.05,5020.66 5655.42,5020.66 5658.42,5023.66 ; 5658.6,5023.82 5658.7,5036.87 5658.36,5050.2 U14.AB32@5668.22,5060.06
  Top Layer w5: UD1.D10@4726.26,5123.31 v3(4738.92,5135.97)
  Inner5 w5: v3(4738.92,5135.97) 4734.42,5135.97 4729.4,5130.95 4729.4,5125.76 4737.92,5117.24 4737.92,5018.24 4776.94,4979.22 5661.41,4979.22 5666.42,4984.23 5666.42,4988.97 5661.42,4993.97 v3(5657.92,4993.97)
SDQS2N: U14.AN23 UD1.V3 | length 741.1
  Top Layer w3: 5337.29,5216.04 5402.98,5216.03 5426.04,5239.09 5438.43,5239.09 5441.43,5236.09 5441.43,5232.72 5444.44,5229.71 5448.68,5229.71 5451.69,5232.72 U14.AN23@5451.69,5237.23
  Top Layer w5: UD1.V3@4946.64,5481.58 4961.92,5496.86 v3(4961.92,5497.97) ; v3(5302.92,5249.97) 5306.92,5249.97 5313.92,5242.97 5313.92,5228.82 5326.7,5216.04 5337.29,5216.04
  内层2 w5: v3(4961.92,5497.97) 4961.92,5500.47 4966.92,5505.47 4973.15,5505.47 4981.65,5496.97 5061.91,5496.97 5076.41,5511.47 5094.43,5511.47 5105.17,5500.73 5105.17,5465.71 5225.42,5345.46 5225.42,5311.41 5268.86,5267.97 5305.41,5267.97 5312.42,5260.96 5312.42,5255.47 5306.92,5249.97 v3(5302.92,5249.97)
SDQS2P: U14.AM23 UD1.W3 | length 740.4
  Top Layer w3: 5339.59,5228.05 5343.84,5228.05 5347.86,5224.03 5399.66,5224.03 5422.72,5247.09 5461.55,5247.05 U14.AM23@5471.37,5237.23
  Top Layer w5: UD1.W3@4946.64,5507.17 4960.05,5520.58 4961.53,5520.58 v3(4961.92,5520.97) ; v3(5325.92,5249.97) 5323.92,5247.97 5323.92,5232.97 5328.92,5227.97 5339.51,5227.97 5339.59,5228.05
  内层2 w5: v3(4961.92,5520.97) 4965.92,5516.97 4977.92,5516.97 4986.42,5508.47 5057.14,5508.47 5071.64,5522.97 5099.2,5522.97 5116.67,5505.5 5116.67,5470.48 5236.92,5350.23 5236.92,5316.18 5273.63,5279.47 5310.18,5279.47 5323.92,5265.73 5323.92,5251.97 v3(5325.92,5249.97)
SDQS3N: U14.AN19 UD1.V10 | length 873.1
  Top Layer w3: 5378.21,5315.99 5396.95,5315.97 5399.95,5312.97 5399.95,5306.23 5402.95,5303.23 5408.94,5303.23 5411.95,5306.24 5411.95,5312.97 5414.95,5315.97 U14.AN19@5451.69,5315.97
  Top Layer w5: UD1.V10@4726.16,5481.58 4726.53,5481.58 v3(4739.92,5494.97) ; v3(5267.17,5306.46) 5276.7,5315.99 5378.21,5315.99
  Inner5 w5: v3(4739.92,5494.97) 4739.92,5499.97 4744.92,5504.97 4752.65,5504.97 4762.15,5495.47 4813.16,5495.47 4819.66,5488.97 4846.19,5488.97 4859.19,5501.97 4914.93,5501.97 4944.93,5471.97 5001.92,5471.97 5019.92,5453.97 5095.92,5453.97 5135.92,5413.97 5175.35,5413.97 5223.92,5365.4 5223.92,5331.98 5243.43,5312.47 5260.64,5312.47 5266.65,5306.46 v3(5267.17,5306.46)
SDQS3P: U14.AM19 UD1.W10 | length 870.7
  Top Layer w3: 5378.21,5325.99 5382.36,5325.99 5384.36,5323.99 5440.54,5323.97 5442.36,5325.79 5457.11,5325.79 5466.93,5315.97 U14.AM19@5471.37,5315.97
  Top Layer w5: UD1.W10@4726.16,5507.17 4727.12,5507.17 v3(4741.92,5521.97) ; v3(5266.92,5326.65) 5267.58,5325.99 5378.21,5325.99
  Inner5 w5: v3(4741.92,5521.97) 4747.42,5516.47 4757.42,5516.47 4766.92,5506.97 4817.93,5506.97 4824.43,5500.47 4841.42,5500.47 4854.42,5513.47 4919.7,5513.47 4949.7,5483.47 5005.53,5483.47 5023.53,5465.47 5100.69,5465.47 5140.69,5425.47 5180.12,5425.47 5235.42,5370.17 5235.42,5336.75 5248.2,5323.97 5264.24,5323.97 v3(5266.92,5326.65)
SPI0-CLK: R123.1 | length 751.8
  Top Layer w4: v1(5648,5958) 5627,5979 5627,6019 5642,6034 5661,6034 5669,6042 5672.06,6042 ccw(c5672.06,6049.5) 5679.56,6049.5 5679.56,6061.5 cw(c5687.06,6061.5) 5694.56,6061.5 5694.56,6049.5 ccw(c5702.06,6049.5) 5709.56,6049.5 5709.56,6061.5 cw(c5717.06,6061.5) 5724.56,6061.5 5724.56,6049.5 ccw(c5732.06,6049.5) 5739.56,6049.5 5739.56,6061.5 cw(c5747.06,6061.5) 5754.56,6061.5 5754.56,6049.5 ccw(c5762.06,6049.5) 5762.06,6042 5878,6042 5900,6020 5900,5996 5916,5980 5916,5806.51 R123.1@5920,5802.51
  Bottom Layer w4: 5611.23,5969 5637,5969 v1(5648,5958)
SPI0-CS: U14.K3 | length 814.8
  Top Layer w3: U14.K3@5904.69,5631.01 5914.96,5641.28 5914.96,5699.52 5928.04,5712.6 5928.04,5767.86 5934,5773.83 5934,5779
  Top Layer w4: v1(5855,6074) 5838,6091 5783,6091 5777.83,6085.83 5777.83,6073.17 5783,6068 5832,6068 5843,6057 5887,6057 5912,6032 5912,6006 5926,5992 5926,5818 5934,5810 5934,5779
  Bottom Layer w4: v1(5855,6074) 5923.77,6074 ; 5910.49,6135 5910.49,6087.28 5923.77,6074 ; 5928.77,6069 5923.77,6074
SPI0-HOLD: U14.N2 | length 626.3
  Top Layer w3: U14.N2@5845.59,5650.71 5862.87,5667.99 5862.87,5747.04 5877,5761.17 5877,5782.3
  Top Layer w4: v1(5656,6003) 5711,5948 5840.04,5948 5877,5911.04 5877,5782.3
  Bottom Layer w4: 5569,6019.49 5610.74,6019.49 5611.23,6019 5640,6019 v1(5656,6003)
SPI0-MISO: U14.L1 | length 657.2
  Top Layer w3: U14.L1@5884.97,5670.43 5881.01,5674.39 5881,5733 5895.89,5747.89 ; 5896,5747.89 5896,5775
  Top Layer w4: v1(5857,5998) 5847,5998 5843,5994 5843,5980 5896,5927 5896,5775
  Bottom Layer w4: v1(5857,5998) 5856,5998 5847,6007 5847,6050 5852,6055 5858,6055 5863,6050 5863,6011.76 5866.1,6008.66 5871.66,6008.66 5875,6012 5875,6050 5878.5,6053.5 5883.5,6053.5 5887,6050 5887,6010 5899,5998 5925,5998 5928.77,6001.77 5928.77,6019
SPI0-MOSI: U14.L2 | length 815.6
  Top Layer w3: U14.L2@5884.96,5650.74 5884.96,5656.51 5895.2,5666.75 5895.2,5674.08 5889,5680.16 5889,5728 5905.5,5744.5 5905.5,5777
  Top Layer w4: v1(5666,5943) 5666,5960 5638,5988 5638,6014 5646,6022 5701,6022 5730,5993 5799,5993 5835,6029 5869,6029 5886,6012 5886,5988 5905.5,5968.5 5905.5,5777
  Bottom Layer w4: 5611.23,5919 5642,5919 v1(5666,5943)
SPI0-WP: U14.M2 | length 766.8
  Top Layer w3: U14.M2@5865.29,5650.71 5871.43,5656.85 5871.43,5743.25 5886.2,5758.02 5886.2,5782
  Top Layer w4: v1(5877,5970) 5871,5976 5871,6004 5861,6014 5842,6014 5830,6002 5830,5976 5886.2,5919.8 5886.2,5782
  Bottom Layer w4: v1(5877,5970) 5865,5970 5850,5955 5850,5908 5855,5903 5862.77,5903 5867,5907.23 5867,5947 5872,5952 5880,5952 5889,5943 5935,5943 5941,5949 5941,5956.77 5928.77,5969 5975.51,5969 5977,5970.49
SPI-LCD-BLK: H1.32 U14.AN9 | length 3640.4
  Top Layer w4: v2(5413,5538) 5426.96,5538 U14.AN9@5452.01,5512.95
  内层2 w5: v2(5189,5990) 5195,5990 5206,6001 5206,6033 5279,6106 5450,6106 5643,5913 5794,5913 5836,5955 5891,5955 5902,5966 6874,5966 7006,5834 v2(7006,5590)
  Bottom Layer w4: H1.32@5159,6343 5166,6343 5208,6301 5208,6210 5189,6191 v2(5189,5990) 5189,5875 5230,5834 5230,5803 5274,5759 5274,5696 5338,5632 5338,5609 5409,5538 v2(5413,5538)
  Bottom Layer w5: 6766.11,5431.15 6766.11,5548.11 6808,5590 v2(7006,5590)
SPI-LCD-CLK: H1.36 TFT1.4 U14.AJ9 | length 3771.4
  Top Layer w4: v1(5511,5533) 5511,5532.71 U14.AJ9@5530.76,5512.95
  Top Layer w5: v2(6973,5260) 7005.68,5227.32 TFT1.4@7005.68,5127.67
  内层2 w5: v2(5228,5959) 5237,5968 5237,6011 5303,6077 5430,6077 5623,5884 5818,5884 5859,5925 5911,5925 5923,5937 6855,5937 6970,5822 6970,5572 6991,5551 6991,5426 6947,5382 6947,5361 6972,5336 6972,5261 v2(6973,5260)
  Bottom Layer w4: H1.36@5359,6343 5359,6337 5312,6290 5312,6226 5274,6188 5251,6188 5228,6165 v2(5228,5959) 5228,5879 5254,5853 5254,5816 5300,5770 5300,5709 5363,5646 5363,5622 5416,5569 5422,5569 5445,5546 5481,5546 5484,5549 5495,5549 v1(5511,5533)
SPI-LCD-CS: H1.33 TFT1.7 U14.AK9 | length 3695.6
  Top Layer w4: v1(5491,5533) U14.AK9@5511.07,5512.95
  Top Layer w5: TFT1.7@6923,5127.67 6923,5239 v2(6927,5243)
  内层2 w5: v2(5208,5974) 5211,5974 5221,5984 5221,6018 5293,6090 5440,6090 5632,5898 5804,5898 5846,5940 5901,5940 5912,5951 6866,5951 6988,5829 6988,5576 7006,5558 7006,5414 6988,5396 6988,5250 6977,5239 6966,5239 6953,5252 6936,5252 v2(6927,5243)
  Bottom Layer w4: H1.33@5259,6243 5259,6230.05 5208,6179.05 v2(5208,5974) 5208,5877 5242,5843 5242,5809 5287,5764 5287,5704 5351,5640 5351,5616 5414,5553 5421,5553 5441,5533 v1(5491,5533)
SPI-LCD-DC: H1.38 TFT1.5 U14.AJ7 | length 3704.7
  Top Layer w4: v1@5512.08,5571 U14.AJ7@5530.76,5552.32
  Top Layer w5: v2(6953,5278) 6953,5253 6978.12,5227.88 TFT1.5@6978.12,5127.67
  内层2 w5: v2(5266,5928) 5266,5996 5320,6050 5418,6050 5612,5856 5841,5856 5879,5894 5925,5894 5939,5908 6837,5908 6932,5813 6932,5555 6961,5526 6961,5449 6914,5402 6914,5329 6953,5290 v2(6953,5278)
  Bottom Layer w3: 5455,5573 5474,5573 5485,5584 5499,5584 v1(5512,5571)
  Bottom Layer w4: 5455,5573 5388,5640 5388,5662 5328,5722 5328,5779 5279,5828 5279,5870 5266,5883 v2(5266,5928) 5266,6140 5277,6151 5296,6151 5337,6192 5389,6192 5412,6215 5412,6297 5429.91,6314.91 5430.91,6314.91 H1.38@5459,6343
SPI-LCD-MOSI: H1.35 TFT1.3 U14.AK7 | length 3602.2
  Top Layer w4: v1(5492,5571) 5492.39,5571 U14.AK7@5511.07,5552.32
  Top Layer w5: v2(6955,5314) 7033.24,5235.76 TFT1.3@7033.24,5127.67
  内层2 w5: v2(5246,5943) 5251,5948 5251,6002 5312,6063 5424,6063 5618,5869 5830,5869 5872,5911 5919,5911 5931,5923 6846,5923 6950,5819 6950,5565 6977,5538 6977,5439 6931,5393 6931,5338 v2(6955,5314)
  Bottom Layer w4: H1.35@5359,6243 5358,6243 5286,6171 5263,6171 5246,6154 v2(5246,5943) 5246,5884 5266,5864 5266,5823 5314,5775 5314,5715 5375,5654 5375,5630 5421,5584 5427,5584 5454,5557 5478,5557 v1(5492,5571)
SPI-LCD-RST: H1.31 TFT1.6 U14.AM9 | length 3739.7
  Top Layer w3: v1(5413,5517) 5433,5517 5447,5503 5461.75,5503 U14.AM9@5471.7,5512.95
  Top Layer w5: TFT1.6@6950.56,5127.67 6951,5128.11 v2(6951,5226)
  内层2 w5: v2(5173,6009) 5173,6021 5273,6121 5458,6121 5653,5926 5780,5926 5828,5974 5858,5974 5870,5986 5894,5986 5898,5982 6880,5982 7024,5838 7024,5340 7004,5320 7004,5240 6984,5220 6957,5220 v2(6951,5226)
  Bottom Layer w4: H1.31@5159,6243 5173,6229 v2(5173,6009) 5173,5871 5220,5824 5220,5797 5262,5755 5262,5693 5326,5629 5326,5604 v1(5413,5517)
